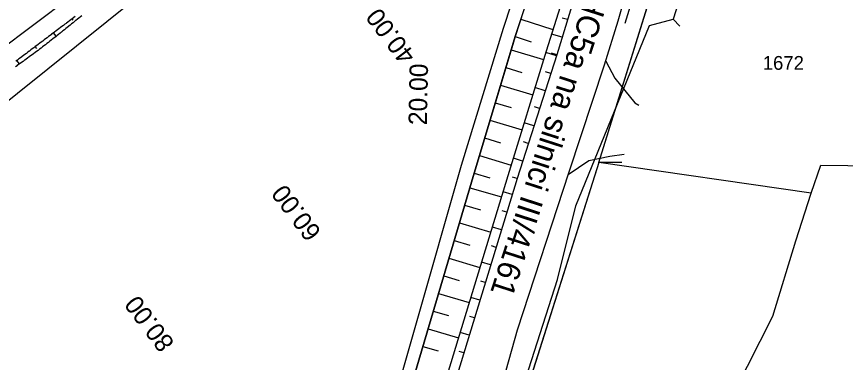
# Model space of a CAD drawing. Extents: x -583470 to -583050, y -1165714 to -1165417.
# Drawn here: x -583260.4 to -583170.4, y -1165584.9 to -1165547.3 of the extents above; entities that cross this region are included whole.
import ezdxf

# ---------------------------------------------------------------- set-up
doc = ezdxf.new("R2010")
doc.units = 0
for name, color, linetype in [('21', 7, 'Continuous'), ('38', 7, 'Continuous'), ('42', 7, 'Continuous'), ('60', 7, 'Continuous'), ('62', 7, 'Continuous'), ('Hranice parcel', 7, 'Continuous'), ('Kabel_soucasny', 7, 'Continuous'), ('Parcelní čísla', 7, 'Continuous'), ('Rám', 7, 'Continuous'), ('Sítě', 7, 'Continuous'), ('Šrafy', 7, 'Continuous')]:
    doc.layers.add(name, color=color, linetype=linetype)

msp = doc.modelspace()

# ---------------------------------------------------------------- linework, layer by layer
at = {"layer": '21'}
for points in [[(-583228.99, -1165653.07), (-583228.87, -1165641.09), (-583228.11, -1165629.9), (-583226.18, -1165618.27), (-583220.81, -1165598.53), (-583210.74, -1165564.34), (-583206.27, -1165549.49), (-583193.05, -1165509.63), (-583187.62, -1165491.96), (-583180.14, -1165470.95), (-583173.68, -1165449.563)], [(-583197.18, -1165563.18), (-583189.57, -1165538.7)], [(-583197.17, -1165563.17), (-583214.79, -1165618.82), (-583215.85, -1165644.01)]]:
    msp.add_lwpolyline(points, dxfattribs=at)
at = {"layer": '38'}
for points in [[(-583175.319, -1165449.443), (-583181.94, -1165470.41), (-583188.9, -1165491.39), (-583194.56, -1165508.91), (-583207.56, -1165548.63), (-583212.15, -1165563.51), (-583221.98, -1165598.06), (-583224.87, -1165608.46), (-583227.16, -1165617.88), (-583229.21, -1165629.48), (-583230.26, -1165654.06)], [(-583186.97, -1165540.85), (-583189.1, -1165547.59)], [(-583188.387, -1165548.347), (-583189.1, -1165547.59)]]:
    msp.add_lwpolyline(points, dxfattribs=at)
at = {"layer": '42'}
for points in [[(-583171.133, -1165449.749), (-583178.31, -1165472.16), (-583184.97, -1165493.01), (-583190.34, -1165511.2), (-583202.91, -1165551.09), (-583207.05, -1165564.64), (-583217.53, -1165598.97), (-583222.81, -1165617.33), (-583225.6, -1165630.49), (-583226.96, -1165652.83), (-583227.01, -1165657.21), (-583226.1, -1165658.69), (-583225.6, -1165663.97)], [(-583194.31, -1165548.02), (-583191.12, -1165537.53), (-583187.24, -1165526.81), (-583176.05, -1165496.65)], [(-583199.68, -1165567.9), (-583191.69, -1165548.3), (-583189.1, -1165547.59)], [(-583209.49, -1165600.28), (-583201.68, -1165575.91), (-583199.68, -1165567.9)]]:
    msp.add_lwpolyline(points, dxfattribs=at)
at = {"layer": '60'}
for points in [[(-583205.64, -1165547.59), (-583202.17, -1165548.74)], [(-583200.59, -1165547.65), (-583201.15, -1165547.48)], [(-583201.18, -1165549.57), (-583202.32, -1165549.22)], [(-583206.27, -1165549.49), (-583204.52, -1165550.07)], [(-583206.7, -1165550.93), (-583203.19, -1165551.99)], [(-583201.79, -1165551.59), (-583202.95, -1165551.22)], [(-583201.76, -1165551.48), (-583202.34, -1165551.3)], [(-583207.28, -1165552.85), (-583205.53, -1165553.38)], [(-583202.41, -1165553.49), (-583202.97, -1165553.31)], [(-583207.86, -1165554.76), (-583204.35, -1165555.82)], [(-583203.02, -1165555.4), (-583204.12, -1165555.04)], [(-583208.43, -1165556.68), (-583206.69, -1165557.21)], [(-583203.63, -1165557.3), (-583204.16, -1165557.13)], [(-583209.01, -1165558.59), (-583205.52, -1165559.64)], [(-583204.24, -1165559.21), (-583205.29, -1165558.87)], [(-583209.59, -1165560.51), (-583207.85, -1165561.03)], [(-583204.85, -1165561.11), (-583205.36, -1165560.95)], [(-583210.16, -1165562.42), (-583206.69, -1165563.47)], [(-583205.46, -1165563.02), (-583206.46, -1165562.7)], [(-583210.74, -1165564.34), (-583209.01, -1165564.86)], [(-583206.07, -1165564.92), (-583206.56, -1165564.76)], [(-583211.2, -1165565.92), (-583207.75, -1165566.93)], [(-583206.6, -1165566.67), (-583207.58, -1165566.37)], [(-583211.77, -1165567.83), (-583210.05, -1165568.34)], [(-583207.19, -1165568.58), (-583207.67, -1165568.43)], [(-583212.33, -1165569.75), (-583208.92, -1165570.76)], [(-583207.77, -1165570.49), (-583208.75, -1165570.2)], [(-583212.9, -1165571.67), (-583211.2, -1165572.17)], [(-583208.35, -1165572.41), (-583208.84, -1165572.26)], [(-583213.46, -1165573.59), (-583210.09, -1165574.58)], [(-583208.94, -1165574.32), (-583209.91, -1165574.02)], [(-583214.03, -1165575.51), (-583212.35, -1165576)], [(-583209.52, -1165576.23), (-583210.01, -1165576.08)], [(-583214.59, -1165577.43), (-583211.25, -1165578.41)], [(-583210.1, -1165578.15), (-583211.08, -1165577.85)], [(-583215.16, -1165579.34), (-583213.5, -1165579.83)], [(-583210.69, -1165580.06), (-583211.18, -1165579.91)], [(-583215.72, -1165581.26), (-583212.42, -1165582.24)], [(-583211.27, -1165581.97), (-583212.25, -1165581.67)], [(-583216.29, -1165583.18), (-583214.65, -1165583.67)], [(-583211.85, -1165583.89), (-583212.34, -1165583.74)]]:
    msp.add_lwpolyline(points, dxfattribs=at)
at = {"layer": '62'}
msp.add_lwpolyline([(-583194.696, -1165563.2), (-583197.17, -1165563.17)], dxfattribs=at)
at = {"layer": 'Parcelní čísla'}
msp.add_line((-583232.311, -1165528.379), (-583286.571, -1165569.38), dxfattribs=at)
at = {"layer": 'Rám'}
msp.add_line((-583174.14, -1165566.51), (-583197.17, -1165563.17), dxfattribs=at)
for points in [[(-583202.69, -1165538.68), (-583225.12, -1165531.51), (-583247.31, -1165545.19), (-583283.21, -1165574.06), (-583292.71, -1165580.22), (-583304.73, -1165581.14), (-583316.86, -1165578.96), (-583335.26, -1165581.29), (-583341.42, -1165583.09), (-583347.21, -1165586.62), (-583351.13, -1165592.35), (-583353.34, -1165595.85), (-583354.98, -1165601.64), (-583352.56, -1165623.43)], [(-583202.69, -1165538.68), (-583205.32, -1165546.6), (-583206.27, -1165549.49), (-583206.64, -1165550.7), (-583210.74, -1165564.34), (-583220.81, -1165598.53), (-583226.18, -1165618.27), (-583228.11, -1165629.9), (-583228.87, -1165641.09), (-583228.99, -1165653.07), (-583228.69, -1165666.2)], [(-583197.17, -1165563.17), (-583191.76, -1165545.76), (-583189.57, -1165538.7)], [(-583197.17, -1165563.17), (-583214.81, -1165618.81), (-583215.85, -1165644.01)], [(-583174.14, -1165566.51), (-583173.07, -1165563.46), (-583161.31, -1165563.6), (-583140.31, -1165584.13)], [(-583189.56, -1165601.59), (-583187.95, -1165599), (-583178.29, -1165579.88), (-583175.8, -1165571.71), (-583174.14, -1165566.51)]]:
    msp.add_lwpolyline(points, dxfattribs=at)
at = {"layer": 'Sítě'}
for points in [[(-583253.323, -1165547.24), (-583253.487, -1165547.358), (-583253.651, -1165547.475), (-583253.808, -1165547.602), (-583253.964, -1165547.73), (-583254.001, -1165547.76), (-583254.12, -1165547.858), (-583254.277, -1165547.985), (-583254.433, -1165548.113), (-583254.59, -1165548.24), (-583254.747, -1165548.367), (-583254.777, -1165548.391), (-583254.904, -1165548.494), (-583255.061, -1165548.621), (-583255.218, -1165548.747), (-583255.376, -1165548.874), (-583255.533, -1165549), (-583255.556, -1165549.018), (-583255.691, -1165549.126), (-583255.849, -1165549.252), (-583256.007, -1165549.377), (-583256.165, -1165549.503), (-583256.323, -1165549.628), (-583256.339, -1165549.641), (-583256.481, -1165549.753), (-583256.64, -1165549.878), (-583256.798, -1165550.003), (-583256.957, -1165550.128), (-583257.116, -1165550.252), (-583257.125, -1165550.259), (-583257.275, -1165550.376), (-583257.434, -1165550.5), (-583257.593, -1165550.624), (-583257.753, -1165550.747), (-583257.917, -1165550.87), (-583258.076, -1165550.989), (-583258.237, -1165551.11), (-583258.399, -1165551.231), (-583258.561, -1165551.351), (-583258.723, -1165551.471), (-583258.885, -1165551.591), (-583259.047, -1165551.711), (-583259.21, -1165551.831), (-583259.372, -1165551.95), (-583259.524, -1165552.061), (-583259.535, -1165552.07), (-583259.698, -1165552.189), (-583259.861, -1165552.308), (-583260.024, -1165552.427), (-583260.187, -1165552.545), (-583260.332, -1165552.65), (-583260.351, -1165552.664), (-583260.514, -1165552.782)], [(-583254.035, -1165547.302), (-583254.196, -1165547.423), (-583254.234, -1165547.452), (-583254.357, -1165547.545), (-583254.518, -1165547.666), (-583254.679, -1165547.788), (-583254.84, -1165547.91), (-583255.001, -1165548.031), (-583255.031, -1165548.054), (-583255.162, -1165548.153), (-583255.323, -1165548.275), (-583255.484, -1165548.396), (-583255.645, -1165548.518), (-583255.806, -1165548.639), (-583255.829, -1165548.657), (-583255.967, -1165548.761), (-583256.127, -1165548.883), (-583256.288, -1165549.004), (-583256.449, -1165549.126), (-583256.61, -1165549.248), (-583256.627, -1165549.26), (-583256.771, -1165549.369), (-583256.932, -1165549.491), (-583257.093, -1165549.613), (-583257.254, -1165549.734), (-583257.415, -1165549.856), (-583257.425, -1165549.863), (-583257.576, -1165549.977), (-583257.737, -1165550.099), (-583257.898, -1165550.221), (-583258.059, -1165550.342), (-583258.22, -1165550.464), (-583258.223, -1165550.466), (-583258.381, -1165550.586), (-583258.542, -1165550.707), (-583258.703, -1165550.829), (-583258.864, -1165550.95), (-583259.021, -1165551.069), (-583259.025, -1165551.072), (-583259.186, -1165551.194), (-583259.347, -1165551.315), (-583259.508, -1165551.437), (-583259.669, -1165551.559), (-583259.818, -1165551.672), (-583259.83, -1165551.68), (-583259.99, -1165551.802), (-583260.151, -1165551.923), (-583260.312, -1165552.045), (-583260.473, -1165552.167)]]:
    msp.add_lwpolyline(points, dxfattribs=at)
at = {"layer": 'Šrafy'}
for p, q in [((-583254.269, -1165547.725), (-583254.388, -1165547.568)), ((-583256.099, -1165549.451), (-583256.383, -1165549.076)), ((-583258.225, -1165550.785), (-583258.377, -1165550.583)), ((-583260.084, -1165552.47), (-583260.372, -1165552.09))]:
    msp.add_line(p, q, dxfattribs=at)
for points in [[(-583170.104, -1165449.824), (-583177.59, -1165472.81), (-583183.72, -1165493.32), (-583189.54, -1165511.52), (-583201.76, -1165551.48), (-583206.07, -1165564.92), (-583216.52, -1165599.19), (-583221.45, -1165616.65), (-583223.99, -1165630.74), (-583225.18, -1165652.54), (-583225.28, -1165659.24), (-583225.23, -1165664)], [(-583220.15, -1165659.61), (-583219.96, -1165653.11), (-583219.97, -1165648.1), (-583219.57, -1165643.1), (-583218.09, -1165630.97), (-583215.53, -1165617.89), (-583214.66, -1165612.9), (-583211.33, -1165600.33), (-583206.01, -1165581.38), (-583200.39, -1165564.2), (-583196.56, -1165552.55), (-583195.08, -1165547.77), (-583192.01, -1165536.91), (-583188.64, -1165525.84), (-583184.8, -1165513.4), (-583179.16, -1165495.16), (-583172.78, -1165474.89), (-583165.038, -1165450.195)], [(-583196.44, -1165552.16), (-583195.45, -1165554.02), (-583193.28, -1165556.7), (-583192.845, -1165556.943)], [(-583200.5, -1165564.48), (-583198.28, -1165562.96), (-583196, -1165562.5), (-583194.425, -1165562.281)]]:
    msp.add_lwpolyline(points, dxfattribs=at)

# ---------------------------------------------------------------- texts
at = {"layer": 'Hranice parcel'}
for s, rotation, p in [('40.00', 127.05657, (-583216.983, -1165551.554)), ('20.00', 88.85939, (-583215.86, -1165559.138)), ('60.00', 127.07651, (-583227.236, -1165570.739)), ('80.00', 127.07651, (-583243.193, -1165582.796))]:
    msp.add_text(s, height=2, rotation=rotation, dxfattribs=at).set_placement(p)
at = {"layer": 'Kabel_soucasny'}
msp.add_text('1672', height=1.5, dxfattribs=at).set_placement((-583179.383, -1165553.106))
at = {"layer": 'Sítě'}
msp.add_text('napojení cesty HC5a na silnici III/4161', height=2.50002, rotation=252.10796, dxfattribs=at).set_placement((-583191.517, -1165523.131))

doc.saveas('drawing.dxf')
